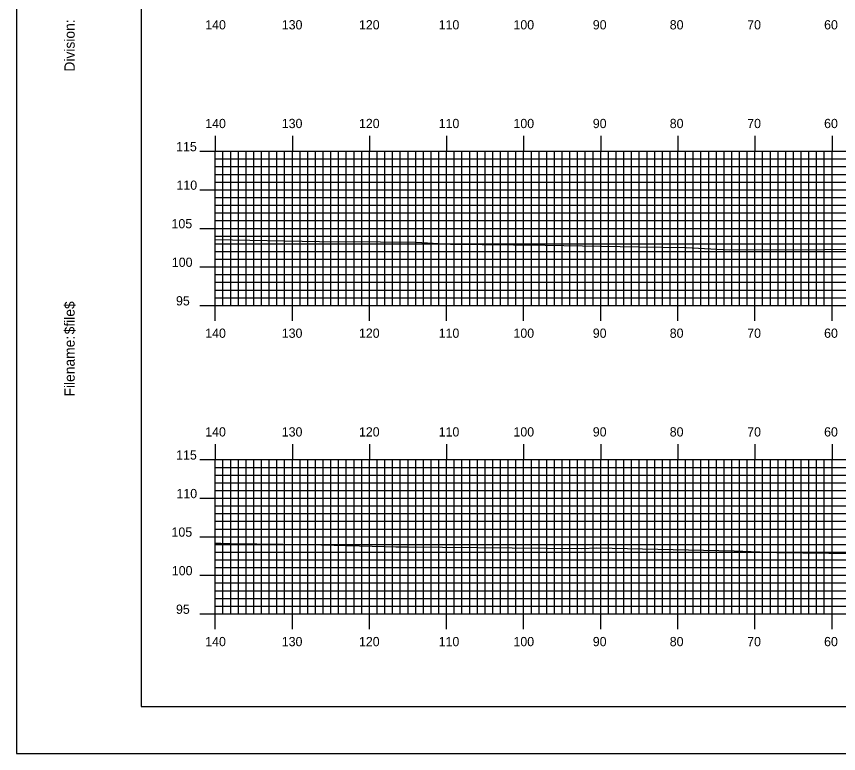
# Model space of a CAD drawing. Extents: x 1773990 to 1774333, y 442591 to 442811.
# Drawn here: x 1773989.9 to 1774096.5, y 442590.5 to 442686.2 of the extents above; entities that cross this region are included whole.
import ezdxf

# ---------------------------------------------------------------- set-up
doc = ezdxf.new("R2010")
doc.units = 0
for name, color, linetype in [('BORDER', 7, 'Continuous'), ('H_V ANNOTATION', 7, 'Continuous'), ('MAJOR', 7, 'Continuous'), ('MINOR', 7, 'Continuous'), ('PLOT BOUNDARY', 7, 'Continuous'), ('S_Roadway_Centerline', 7, 'Continuous')]:
    doc.layers.add(name, color=color, linetype=linetype)

msp = doc.modelspace()

# ---------------------------------------------------------------- linework, layer by layer
at = {"layer": 'BORDER'}
msp.add_lwpolyline([(1774006.06, 442596.67), (1774326.06, 442596.67), (1774326.06, 442806.67), (1774006.06, 442806.67)], close=True, dxfattribs=at)
at = {"layer": 'MAJOR'}
for p, q in [((1774015.66, 442670.67), (1774015.66, 442668.67)), ((1774025.66, 442670.67), (1774025.66, 442668.67)), ((1774035.66, 442670.67), (1774035.66, 442668.67)), ((1774045.66, 442670.67), (1774045.66, 442668.67)), ((1774055.66, 442670.67), (1774055.66, 442668.67)), ((1774065.66, 442670.67), (1774065.66, 442668.67)), ((1774075.66, 442670.67), (1774075.66, 442668.67)), ((1774085.66, 442670.67), (1774085.66, 442668.67)), ((1774095.66, 442670.67), (1774095.66, 442668.67)), ((1774013.65, 442668.67), (1774015.66, 442668.67)), ((1774015.66, 442668.67), (1774295.66, 442668.67)), ((1774015.66, 442648.67), (1774015.66, 442668.67)), ((1774015.66, 442648.67), (1774015.66, 442668.67)), ((1774015.66, 442668.67), (1774295.66, 442668.67)), ((1774025.66, 442648.67), (1774025.66, 442668.67)), ((1774035.66, 442648.67), (1774035.66, 442668.67)), ((1774045.66, 442648.67), (1774045.66, 442668.67)), ((1774055.66, 442648.67), (1774055.66, 442668.67)), ((1774065.66, 442648.67), (1774065.66, 442668.67)), ((1774075.66, 442648.67), (1774075.66, 442668.67)), ((1774085.66, 442648.67), (1774085.66, 442668.67)), ((1774095.66, 442648.67), (1774095.66, 442668.67)), ((1774013.65, 442663.67), (1774015.66, 442663.67)), ((1774015.66, 442663.67), (1774295.66, 442663.67)), ((1774013.65, 442658.67), (1774015.66, 442658.67)), ((1774015.66, 442658.67), (1774295.66, 442658.67)), ((1774013.65, 442653.67), (1774015.66, 442653.67)), ((1774015.66, 442653.67), (1774295.66, 442653.67)), ((1774013.65, 442648.67), (1774015.66, 442648.67)), ((1774015.66, 442648.67), (1774295.66, 442648.67)), ((1774015.66, 442648.67), (1774295.66, 442648.67)), ((1774015.66, 442646.66), (1774015.66, 442648.67)), ((1774025.66, 442646.66), (1774025.66, 442648.67)), ((1774035.66, 442646.66), (1774035.66, 442648.67)), ((1774045.66, 442646.66), (1774045.66, 442648.67)), ((1774055.66, 442646.66), (1774055.66, 442648.67)), ((1774065.66, 442646.66), (1774065.66, 442648.67)), ((1774075.66, 442646.66), (1774075.66, 442648.67)), ((1774085.66, 442646.66), (1774085.66, 442648.67)), ((1774095.66, 442646.66), (1774095.66, 442648.67)), ((1774015.66, 442630.67), (1774015.66, 442628.67)), ((1774025.66, 442630.67), (1774025.66, 442628.67)), ((1774035.66, 442630.67), (1774035.66, 442628.67)), ((1774045.66, 442630.67), (1774045.66, 442628.67)), ((1774055.66, 442630.67), (1774055.66, 442628.67)), ((1774065.66, 442630.67), (1774065.66, 442628.67)), ((1774075.66, 442630.67), (1774075.66, 442628.67)), ((1774085.66, 442630.67), (1774085.66, 442628.67)), ((1774095.66, 442630.67), (1774095.66, 442628.67)), ((1774013.65, 442628.67), (1774015.66, 442628.67)), ((1774015.66, 442628.67), (1774295.66, 442628.67)), ((1774015.66, 442608.67), (1774015.66, 442628.67)), ((1774015.66, 442608.67), (1774015.66, 442628.67)), ((1774015.66, 442628.67), (1774295.66, 442628.67)), ((1774025.66, 442608.67), (1774025.66, 442628.67)), ((1774035.66, 442608.67), (1774035.66, 442628.67)), ((1774045.66, 442608.67), (1774045.66, 442628.67)), ((1774055.66, 442608.67), (1774055.66, 442628.67)), ((1774065.66, 442608.67), (1774065.66, 442628.67)), ((1774075.66, 442608.67), (1774075.66, 442628.67)), ((1774085.66, 442608.67), (1774085.66, 442628.67)), ((1774095.66, 442608.67), (1774095.66, 442628.67)), ((1774013.65, 442623.67), (1774015.66, 442623.67)), ((1774015.66, 442623.67), (1774295.66, 442623.67)), ((1774013.65, 442618.67), (1774015.66, 442618.67)), ((1774015.66, 442618.67), (1774295.66, 442618.67)), ((1774013.65, 442613.67), (1774015.66, 442613.67)), ((1774015.66, 442613.67), (1774295.66, 442613.67)), ((1774013.65, 442608.67), (1774015.66, 442608.67)), ((1774015.66, 442608.67), (1774295.66, 442608.67)), ((1774015.66, 442608.67), (1774295.66, 442608.67)), ((1774015.66, 442606.66), (1774015.66, 442608.67)), ((1774025.66, 442606.66), (1774025.66, 442608.67)), ((1774035.66, 442606.66), (1774035.66, 442608.67)), ((1774045.66, 442606.66), (1774045.66, 442608.67)), ((1774055.66, 442606.66), (1774055.66, 442608.67)), ((1774065.66, 442606.66), (1774065.66, 442608.67)), ((1774075.66, 442606.66), (1774075.66, 442608.67)), ((1774085.66, 442606.66), (1774085.66, 442608.67)), ((1774095.66, 442606.66), (1774095.66, 442608.67))]:
    msp.add_line(p, q, dxfattribs=at)
at = {"layer": 'MINOR'}
for p, q in [((1774016.66, 442648.67), (1774016.66, 442668.67)), ((1774017.66, 442648.67), (1774017.66, 442668.67)), ((1774018.66, 442648.67), (1774018.66, 442668.67)), ((1774019.66, 442648.67), (1774019.66, 442668.67)), ((1774020.66, 442648.67), (1774020.66, 442668.67)), ((1774021.66, 442648.67), (1774021.66, 442668.67)), ((1774022.66, 442648.67), (1774022.66, 442668.67)), ((1774023.66, 442648.67), (1774023.66, 442668.67)), ((1774024.66, 442648.67), (1774024.66, 442668.67)), ((1774026.66, 442648.67), (1774026.66, 442668.67)), ((1774027.66, 442648.67), (1774027.66, 442668.67)), ((1774028.66, 442648.67), (1774028.66, 442668.67)), ((1774029.66, 442648.67), (1774029.66, 442668.67)), ((1774030.66, 442648.67), (1774030.66, 442668.67)), ((1774031.66, 442648.67), (1774031.66, 442668.67)), ((1774032.66, 442648.67), (1774032.66, 442668.67)), ((1774033.66, 442648.67), (1774033.66, 442668.67)), ((1774034.66, 442648.67), (1774034.66, 442668.67)), ((1774036.66, 442648.67), (1774036.66, 442668.67)), ((1774037.66, 442648.67), (1774037.66, 442668.67)), ((1774038.66, 442648.67), (1774038.66, 442668.67)), ((1774039.66, 442648.67), (1774039.66, 442668.67)), ((1774040.66, 442648.67), (1774040.66, 442668.67)), ((1774041.66, 442648.67), (1774041.66, 442668.67)), ((1774042.66, 442648.67), (1774042.66, 442668.67)), ((1774043.66, 442648.67), (1774043.66, 442668.67)), ((1774044.66, 442648.67), (1774044.66, 442668.67)), ((1774046.66, 442648.67), (1774046.66, 442668.67)), ((1774047.66, 442648.67), (1774047.66, 442668.67)), ((1774048.66, 442648.67), (1774048.66, 442668.67)), ((1774049.66, 442648.67), (1774049.66, 442668.67)), ((1774050.66, 442648.67), (1774050.66, 442668.67)), ((1774051.66, 442648.67), (1774051.66, 442668.67)), ((1774052.66, 442648.67), (1774052.66, 442668.67)), ((1774053.66, 442648.67), (1774053.66, 442668.67)), ((1774054.66, 442648.67), (1774054.66, 442668.67)), ((1774056.66, 442648.67), (1774056.66, 442668.67)), ((1774057.66, 442648.67), (1774057.66, 442668.67)), ((1774058.66, 442648.67), (1774058.66, 442668.67)), ((1774059.66, 442648.67), (1774059.66, 442668.67)), ((1774060.66, 442648.67), (1774060.66, 442668.67)), ((1774061.66, 442648.67), (1774061.66, 442668.67)), ((1774062.66, 442648.67), (1774062.66, 442668.67)), ((1774063.66, 442648.67), (1774063.66, 442668.67)), ((1774064.66, 442648.67), (1774064.66, 442668.67)), ((1774066.66, 442648.67), (1774066.66, 442668.67)), ((1774067.66, 442648.67), (1774067.66, 442668.67)), ((1774068.66, 442648.67), (1774068.66, 442668.67)), ((1774069.66, 442648.67), (1774069.66, 442668.67)), ((1774070.66, 442648.67), (1774070.66, 442668.67)), ((1774071.66, 442648.67), (1774071.66, 442668.67)), ((1774072.66, 442648.67), (1774072.66, 442668.67)), ((1774073.66, 442648.67), (1774073.66, 442668.67)), ((1774074.66, 442648.67), (1774074.66, 442668.67)), ((1774076.66, 442648.67), (1774076.66, 442668.67)), ((1774077.66, 442648.67), (1774077.66, 442668.67)), ((1774078.66, 442648.67), (1774078.66, 442668.67)), ((1774079.66, 442648.67), (1774079.66, 442668.67)), ((1774080.66, 442648.67), (1774080.66, 442668.67)), ((1774081.66, 442648.67), (1774081.66, 442668.67)), ((1774082.66, 442648.67), (1774082.66, 442668.67)), ((1774083.66, 442648.67), (1774083.66, 442668.67)), ((1774084.66, 442648.67), (1774084.66, 442668.67)), ((1774086.66, 442648.67), (1774086.66, 442668.67)), ((1774087.66, 442648.67), (1774087.66, 442668.67)), ((1774088.66, 442648.67), (1774088.66, 442668.67)), ((1774089.66, 442648.67), (1774089.66, 442668.67)), ((1774090.66, 442648.67), (1774090.66, 442668.67)), ((1774091.66, 442648.67), (1774091.66, 442668.67)), ((1774092.66, 442648.67), (1774092.66, 442668.67)), ((1774093.66, 442648.67), (1774093.66, 442668.67)), ((1774094.66, 442648.67), (1774094.66, 442668.67)), ((1774015.66, 442667.67), (1774295.66, 442667.67)), ((1774015.66, 442667.67), (1774017.66, 442667.67)), ((1774015.66, 442666.67), (1774295.66, 442666.67)), ((1774015.66, 442666.67), (1774017.66, 442666.67)), ((1774015.66, 442665.67), (1774295.66, 442665.67)), ((1774015.66, 442665.67), (1774017.66, 442665.67)), ((1774015.66, 442664.67), (1774295.66, 442664.67)), ((1774015.66, 442664.67), (1774017.66, 442664.67)), ((1774015.66, 442662.67), (1774295.66, 442662.67)), ((1774015.66, 442662.67), (1774017.66, 442662.67)), ((1774015.66, 442661.67), (1774295.66, 442661.67)), ((1774015.66, 442661.67), (1774017.66, 442661.67)), ((1774015.66, 442660.67), (1774295.66, 442660.67)), ((1774015.66, 442660.67), (1774017.66, 442660.67)), ((1774015.66, 442659.67), (1774295.66, 442659.67)), ((1774015.66, 442659.67), (1774017.66, 442659.67)), ((1774015.66, 442657.67), (1774295.66, 442657.67)), ((1774015.66, 442657.67), (1774017.66, 442657.67)), ((1774015.66, 442656.67), (1774295.66, 442656.67)), ((1774015.66, 442656.67), (1774017.66, 442656.67)), ((1774015.66, 442655.67), (1774295.66, 442655.67)), ((1774015.66, 442655.67), (1774017.66, 442655.67)), ((1774015.66, 442654.67), (1774295.66, 442654.67)), ((1774015.66, 442654.67), (1774017.66, 442654.67)), ((1774015.66, 442652.67), (1774295.66, 442652.67)), ((1774015.66, 442652.67), (1774017.66, 442652.67)), ((1774015.66, 442651.67), (1774295.66, 442651.67)), ((1774015.66, 442651.67), (1774017.66, 442651.67)), ((1774015.66, 442650.67), (1774295.66, 442650.67)), ((1774015.66, 442650.67), (1774017.66, 442650.67)), ((1774015.66, 442649.67), (1774295.66, 442649.67)), ((1774015.66, 442649.67), (1774017.66, 442649.67)), ((1774016.66, 442608.67), (1774016.66, 442628.67)), ((1774017.66, 442608.67), (1774017.66, 442628.67)), ((1774018.66, 442608.67), (1774018.66, 442628.67)), ((1774019.66, 442608.67), (1774019.66, 442628.67)), ((1774020.66, 442608.67), (1774020.66, 442628.67)), ((1774021.66, 442608.67), (1774021.66, 442628.67)), ((1774022.66, 442608.67), (1774022.66, 442628.67)), ((1774023.66, 442608.67), (1774023.66, 442628.67)), ((1774024.66, 442608.67), (1774024.66, 442628.67)), ((1774026.66, 442608.67), (1774026.66, 442628.67)), ((1774027.66, 442608.67), (1774027.66, 442628.67)), ((1774028.66, 442608.67), (1774028.66, 442628.67)), ((1774029.66, 442608.67), (1774029.66, 442628.67)), ((1774030.66, 442608.67), (1774030.66, 442628.67)), ((1774031.66, 442608.67), (1774031.66, 442628.67)), ((1774032.66, 442608.67), (1774032.66, 442628.67)), ((1774033.66, 442608.67), (1774033.66, 442628.67)), ((1774034.66, 442608.67), (1774034.66, 442628.67)), ((1774036.66, 442608.67), (1774036.66, 442628.67)), ((1774037.66, 442608.67), (1774037.66, 442628.67)), ((1774038.66, 442608.67), (1774038.66, 442628.67)), ((1774039.66, 442608.67), (1774039.66, 442628.67)), ((1774040.66, 442608.67), (1774040.66, 442628.67)), ((1774041.66, 442608.67), (1774041.66, 442628.67)), ((1774042.66, 442608.67), (1774042.66, 442628.67)), ((1774043.66, 442608.67), (1774043.66, 442628.67)), ((1774044.66, 442608.67), (1774044.66, 442628.67)), ((1774046.66, 442608.67), (1774046.66, 442628.67)), ((1774047.66, 442608.67), (1774047.66, 442628.67)), ((1774048.66, 442608.67), (1774048.66, 442628.67)), ((1774049.66, 442608.67), (1774049.66, 442628.67)), ((1774050.66, 442608.67), (1774050.66, 442628.67)), ((1774051.66, 442608.67), (1774051.66, 442628.67)), ((1774052.66, 442608.67), (1774052.66, 442628.67)), ((1774053.66, 442608.67), (1774053.66, 442628.67)), ((1774054.66, 442608.67), (1774054.66, 442628.67)), ((1774056.66, 442608.67), (1774056.66, 442628.67)), ((1774057.66, 442608.67), (1774057.66, 442628.67)), ((1774058.66, 442608.67), (1774058.66, 442628.67)), ((1774059.66, 442608.67), (1774059.66, 442628.67)), ((1774060.66, 442608.67), (1774060.66, 442628.67)), ((1774061.66, 442608.67), (1774061.66, 442628.67)), ((1774062.66, 442608.67), (1774062.66, 442628.67)), ((1774063.66, 442608.67), (1774063.66, 442628.67)), ((1774064.66, 442608.67), (1774064.66, 442628.67)), ((1774066.66, 442608.67), (1774066.66, 442628.67)), ((1774067.66, 442608.67), (1774067.66, 442628.67)), ((1774068.66, 442608.67), (1774068.66, 442628.67)), ((1774069.66, 442608.67), (1774069.66, 442628.67)), ((1774070.66, 442608.67), (1774070.66, 442628.67)), ((1774071.66, 442608.67), (1774071.66, 442628.67)), ((1774072.66, 442608.67), (1774072.66, 442628.67)), ((1774073.66, 442608.67), (1774073.66, 442628.67)), ((1774074.66, 442608.67), (1774074.66, 442628.67)), ((1774076.66, 442608.67), (1774076.66, 442628.67)), ((1774077.66, 442608.67), (1774077.66, 442628.67)), ((1774078.66, 442608.67), (1774078.66, 442628.67)), ((1774079.66, 442608.67), (1774079.66, 442628.67)), ((1774080.66, 442608.67), (1774080.66, 442628.67)), ((1774081.66, 442608.67), (1774081.66, 442628.67)), ((1774082.66, 442608.67), (1774082.66, 442628.67)), ((1774083.66, 442608.67), (1774083.66, 442628.67)), ((1774084.66, 442608.67), (1774084.66, 442628.67)), ((1774086.66, 442608.67), (1774086.66, 442628.67)), ((1774087.66, 442608.67), (1774087.66, 442628.67)), ((1774088.66, 442608.67), (1774088.66, 442628.67)), ((1774089.66, 442608.67), (1774089.66, 442628.67)), ((1774090.66, 442608.67), (1774090.66, 442628.67)), ((1774091.66, 442608.67), (1774091.66, 442628.67)), ((1774092.66, 442608.67), (1774092.66, 442628.67)), ((1774093.66, 442608.67), (1774093.66, 442628.67)), ((1774094.66, 442608.67), (1774094.66, 442628.67)), ((1774015.66, 442627.67), (1774295.66, 442627.67)), ((1774015.66, 442627.67), (1774017.66, 442627.67)), ((1774015.66, 442626.67), (1774295.66, 442626.67)), ((1774015.66, 442626.67), (1774017.66, 442626.67)), ((1774015.66, 442625.67), (1774295.66, 442625.67)), ((1774015.66, 442625.67), (1774017.66, 442625.67)), ((1774015.66, 442624.67), (1774295.66, 442624.67)), ((1774015.66, 442624.67), (1774017.66, 442624.67)), ((1774015.66, 442622.67), (1774295.66, 442622.67)), ((1774015.66, 442622.67), (1774017.66, 442622.67)), ((1774015.66, 442621.67), (1774295.66, 442621.67)), ((1774015.66, 442621.67), (1774017.66, 442621.67)), ((1774015.66, 442620.67), (1774295.66, 442620.67)), ((1774015.66, 442620.67), (1774017.66, 442620.67)), ((1774015.66, 442619.67), (1774295.66, 442619.67)), ((1774015.66, 442619.67), (1774017.66, 442619.67)), ((1774015.66, 442617.67), (1774295.66, 442617.67)), ((1774015.66, 442617.67), (1774017.66, 442617.67)), ((1774015.66, 442616.67), (1774295.66, 442616.67)), ((1774015.66, 442616.67), (1774017.66, 442616.67)), ((1774015.66, 442615.67), (1774295.66, 442615.67)), ((1774015.66, 442615.67), (1774017.66, 442615.67)), ((1774015.66, 442614.67), (1774295.66, 442614.67)), ((1774015.66, 442614.67), (1774017.66, 442614.67)), ((1774015.66, 442612.67), (1774295.66, 442612.67)), ((1774015.66, 442612.67), (1774017.66, 442612.67)), ((1774015.66, 442611.67), (1774295.66, 442611.67)), ((1774015.66, 442611.67), (1774017.66, 442611.67)), ((1774015.66, 442610.67), (1774295.66, 442610.67)), ((1774015.66, 442610.67), (1774017.66, 442610.67)), ((1774015.66, 442609.67), (1774295.66, 442609.67)), ((1774015.66, 442609.67), (1774017.66, 442609.67))]:
    msp.add_line(p, q, dxfattribs=at)
at = {"layer": 'PLOT BOUNDARY'}
msp.add_lwpolyline([(1773989.87, 442590.55), (1774329.87, 442590.55), (1774329.87, 442810.55), (1773989.87, 442810.55)], close=True, dxfattribs=at)
at = {"layer": 'S_Roadway_Centerline'}
for points in [[(1774015.66, 442657.23), (1774029.16, 442656.95), (1774037.11, 442656.93), (1774041.73, 442656.86), (1774046.17, 442656.61), (1774058.46, 442656.47), (1774070.61, 442656.25), (1774076.73, 442656.2), (1774082.32, 442655.87), (1774094.6, 442655.94), (1774103.95, 442655.99), (1774118.87, 442655.38), (1774126.26, 442655.22), (1774134.24, 442655.31), (1774142.03, 442655.1), (1774148.27, 442654.99), (1774156.75, 442654.91), (1774168.54, 442655.07), (1774170.6, 442655.09), (1774172.16, 442655.08), (1774191.44, 442654.47), (1774193.51, 442654.38), (1774213.52, 442654.06)], [(1774015.66, 442617.85), (1774016.38, 442617.85), (1774017.68, 442617.8), (1774027.81, 442617.68), (1774037.65, 442617.39), (1774039.1, 442617.35), (1774040.58, 442617.34), (1774063.22, 442617.15), (1774065.17, 442617.21), (1774082.96, 442616.86), (1774088.49, 442616.63), (1774105.3, 442616.43)]]:
    msp.add_lwpolyline(points, dxfattribs=at)

# ---------------------------------------------------------------- texts
at = {"layer": 'BORDER'}
for s, p in [('Division:', (1773997.43, 442679)), ('$file$', (1773997.43, 442644.92)), ('Filename:', (1773997.43, 442636.86))]:
    msp.add_text(s, height=1.339, rotation=90, dxfattribs=at).set_placement(p)
at = {"layer": 'H_V ANNOTATION'}
for s, p in [('140', (1774014.36, 442684.47)), ('130', (1774024.29, 442684.47)), ('120', (1774034.3, 442684.47)), ('110', (1774044.64, 442684.47)), ('100', (1774054.34, 442684.47)), ('90', (1774064.63, 442684.47)), ('80', (1774074.61, 442684.47)), ('70', (1774084.66, 442684.47)), ('60', (1774094.63, 442684.47)), ('140', (1774014.36, 442671.67)), ('130', (1774024.29, 442671.67)), ('120', (1774034.3, 442671.67)), ('110', (1774044.64, 442671.67)), ('100', (1774054.34, 442671.67)), ('90', (1774064.63, 442671.67)), ('80', (1774074.61, 442671.67)), ('70', (1774084.66, 442671.67)), ('60', (1774094.63, 442671.67)), ('115', (1774010.59, 442668.67)), ('110', (1774010.63, 442663.67)), ('105', (1774009.99, 442658.67)), ('100', (1774010.03, 442653.67)), ('95', (1774010.57, 442648.67)), ('140', (1774014.36, 442644.47)), ('130', (1774024.29, 442644.47)), ('120', (1774034.3, 442644.47)), ('110', (1774044.64, 442644.47)), ('100', (1774054.34, 442644.47)), ('90', (1774064.63, 442644.47)), ('80', (1774074.61, 442644.47)), ('70', (1774084.66, 442644.47)), ('60', (1774094.63, 442644.47)), ('140', (1774014.36, 442631.67)), ('130', (1774024.29, 442631.67)), ('120', (1774034.3, 442631.67)), ('110', (1774044.64, 442631.67)), ('100', (1774054.34, 442631.67)), ('90', (1774064.63, 442631.67)), ('80', (1774074.61, 442631.67)), ('70', (1774084.66, 442631.67)), ('60', (1774094.63, 442631.67)), ('115', (1774010.59, 442628.67)), ('110', (1774010.63, 442623.67)), ('105', (1774009.99, 442618.67)), ('100', (1774010.03, 442613.67)), ('95', (1774010.57, 442608.67)), ('140', (1774014.36, 442604.47)), ('130', (1774024.29, 442604.47)), ('120', (1774034.3, 442604.47)), ('110', (1774044.64, 442604.47)), ('100', (1774054.34, 442604.47)), ('90', (1774064.63, 442604.47)), ('80', (1774074.61, 442604.47)), ('70', (1774084.66, 442604.47)), ('60', (1774094.63, 442604.47))]:
    msp.add_text(s, height=1.2, dxfattribs=at).set_placement(p)
at = {"layer": 'MAJOR'}
for p in [(1774015.65, 442648.67), (1774015.65, 442608.67)]:
    msp.add_text('-', height=0.012, dxfattribs=at).set_placement(p)

doc.saveas('drawing.dxf')
